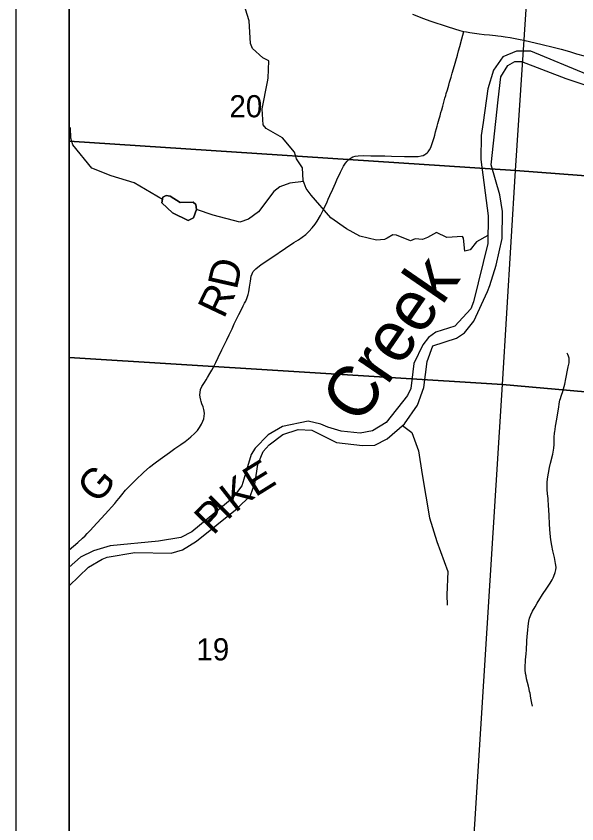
# Model space of a CAD drawing. Extents: x 0 to 34, y 0 to 22.
# Drawn here: x 23.417 to 24.476, y 16.271 to 17.797 of the extents above; entities that cross this region are included whole.
import ezdxf

# ---------------------------------------------------------------- set-up
doc = ezdxf.new("R2010")
doc.units = 0
for name, color, linetype in [('Default', 7, 'Continuous'), ('GM_X_County_Road', 7, 'Continuous'), ('GM_X_County_Road_Text', 7, 'Continuous'), ('GM_X_Major_River', 7, 'Continuous'), ('GM_X_Major_River_Text', 7, 'Continuous'), ('GM_X_Minor_River', 7, 'Continuous'), ('GM_X_Section', 7, 'Continuous'), ('GM_X_Section_Text', 7, 'Continuous'), ('GM_X_Township_Road', 7, 'Continuous'), ('GM_X_Township_Road_Text', 7, 'Continuous'), ('SH_Data', 7, 'Continuous'), ('SH_Text', 7, 'Continuous')]:
    doc.layers.add(name, color=color, linetype=linetype)

msp = doc.modelspace()

# ---------------------------------------------------------------- linework, layer by layer
at = {"layer": 'Default'}
msp.add_lwpolyline([(27.7198, 20.9), (23.5167, 20.9), (23.5167, 16.1239), (23.5888, 16.1195), (25.0535, 16.0331), (25.3458, 16.0191), (26.0811, 15.9921), (26.3691, 15.9829), (26.8773, 15.953), (26.8866, 15.9536), (26.8953, 15.9537)], dxfattribs=at)
for points in [[(23.5167, 17.973), (23.5167, 17.5604), (24.3605, 17.505), (24.3871, 17.9146)], [(23.5167, 17.5604), (23.5167, 17.1515), (24.3357, 17.1007), (24.3605, 17.505)], [(23.5167, 17.1515), (23.5167, 16.1254), (24.2716, 16.0795), (24.3357, 17.1007)]]:
    msp.add_lwpolyline(points, close=True, dxfattribs=at)
at = {"layer": 'GM_X_County_Road'}
for points in [[(24.1653, 17.8003), (24.1861, 17.7921), (24.1983, 17.7879), (24.2332, 17.7767), (24.2551, 17.7699), (24.2629, 17.7678)], [(24.2629, 17.7678), (24.2678, 17.7668), (24.2737, 17.7657), (24.2828, 17.7643), (24.2916, 17.7633), (24.3012, 17.7623), (24.3111, 17.7613), (24.3224, 17.7603), (24.327, 17.7598), (24.3331, 17.7591), (24.3405, 17.7579), (24.3499, 17.7564), (24.3689, 17.7529), (24.3762, 17.7514), (24.4107, 17.7433), (24.4312, 17.738), (24.4466, 17.7343), (24.4621, 17.7298), (24.4755, 17.7258), (24.4898, 17.7216)]]:
    msp.add_lwpolyline(points, dxfattribs=at)
at = {"layer": 'GM_X_Major_River'}
for points in [[(24.4957, 17.6864), (24.3895, 17.7308), (24.3622, 17.7307), (24.3365, 17.7196), (24.3184, 17.6949), (24.3078, 17.6592), (24.2993, 17.5961), (24.2956, 17.5711), (24.295, 17.5259), (24.3089, 17.4194), (24.3079, 17.367), (24.281, 17.2572), (24.2757, 17.2439), (24.2459, 17.2108), (24.2095, 17.1997), (24.1959, 17.1894), (24.1854, 17.1757), (24.168, 17.1407), (24.1625, 17.0929), (24.1561, 17.0799), (24.1157, 17.0289), (24.09, 17.0133), (24.0665, 17.009), (24.0309, 17.0123), (24.0055, 17.0202), (23.9926, 17.0258), (23.9687, 17.0314), (23.9199, 17.0214), (23.893, 17.0057), (23.8681, 16.9806), (23.8605, 16.9684), (23.8467, 16.9217), (23.8429, 16.9091), (23.8248, 16.8852), (23.7484, 16.8223), (23.728, 16.8119), (23.6856, 16.805), (23.5943, 16.7959), (23.5629, 16.7863), (23.5383, 16.7744), (23.5167, 16.7555)], [(24.3328, 17.682), (24.3456, 17.7033), (24.3588, 17.711), (24.3717, 17.711), (24.4552, 17.6791), (24.4665, 17.6753), (24.592, 17.6329)], [(23.5167, 16.7202), (23.5535, 16.7555), (23.5789, 16.7708), (23.5887, 16.7742), (23.641, 16.7835), (23.7095, 16.7823), (23.7311, 16.7884), (23.7576, 16.8049), (23.8343, 16.8666), (23.8596, 16.891), (23.8683, 16.9161), (23.8735, 16.9499), (23.8833, 16.9742), (23.895, 16.9867), (23.9203, 17.0062), (23.9494, 17.0158), (23.9752, 17.0147), (24.0222, 16.9914), (24.0711, 16.9855), (24.0946, 16.986), (24.118, 16.9982), (24.1505, 17.0264), (24.1751, 17.0614), (24.1871, 17.0948), (24.1904, 17.1199), (24.1934, 17.1442), (24.2039, 17.1738), (24.249, 17.1884), (24.2637, 17.1983), (24.2814, 17.2204), (24.3074, 17.2767), (24.3119, 17.2877), (24.3239, 17.3264), (24.3348, 17.3769), (24.3358, 17.4274), (24.3304, 17.4589), (24.3143, 17.5158), (24.3272, 17.6388), (24.3328, 17.682)]]:
    msp.add_lwpolyline(points, dxfattribs=at)
at = {"layer": 'GM_X_Minor_River'}
for points in [[(24.308, 17.3824), (24.2865, 17.3703), (24.2748, 17.3554), (24.2645, 17.3524), (24.2619, 17.3771), (24.26, 17.3805), (24.2304, 17.3786), (24.2111, 17.3881), (24.1937, 17.3785), (24.1846, 17.3747), (24.1705, 17.3759), (24.1618, 17.372), (24.1353, 17.383), (24.1285, 17.3838), (24.1175, 17.3773), (24.1129, 17.375), (24.0978, 17.3735), (24.0659, 17.3811), (24.0409, 17.3947), (24.0113, 17.4156), (23.9742, 17.4585), (23.9644, 17.4714), (23.9591, 17.4859), (23.9576, 17.5102), (23.9466, 17.5269), (23.9424, 17.5398), (23.92, 17.5668), (23.8894, 17.5846), (23.8833, 17.5911), (23.8818, 17.6215), (23.8917, 17.6729), (23.8928, 17.6793), (23.8943, 17.712), (23.883, 17.7181), (23.8633, 17.7356), (23.8598, 17.7451), (23.8568, 17.7876), (23.8436, 17.831)], [(23.6933, 17.45), (23.6399, 17.4817), (23.5963, 17.495), (23.5599, 17.5097), (23.5235, 17.5538), (23.5198, 17.566), (23.5194, 17.5861)], [(23.9597, 17.4842), (23.9337, 17.4809), (23.9147, 17.474), (23.9037, 17.4657), (23.8745, 17.4268), (23.8556, 17.4131), (23.8396, 17.4074), (23.7892, 17.421), (23.7574, 17.4313)], [(23.7574, 17.4313), (23.7521, 17.4157), (23.7415, 17.4107), (23.7123, 17.4251), (23.6922, 17.4441), (23.6941, 17.4544), (23.7002, 17.4578), (23.7074, 17.4567), (23.7263, 17.4449), (23.7513, 17.445), (23.7562, 17.4408), (23.7574, 17.4313)], [(23.6941, 17.4544), (23.6922, 17.4441), (23.7123, 17.4251), (23.7415, 17.4107), (23.7521, 17.4157), (23.7574, 17.4313)], [(23.7574, 17.4313), (23.7562, 17.4408), (23.7513, 17.445), (23.7263, 17.4449), (23.7074, 17.4567), (23.7002, 17.4578), (23.6941, 17.4544)], [(24.147, 17.0235), (24.1643, 17.0101), (24.1768, 16.9755), (24.184, 16.9307), (24.198, 16.8489), (24.2116, 16.8041), (24.2325, 16.7474), (24.2302, 16.7033), (24.2309, 16.6839)]]:
    msp.add_lwpolyline(points, dxfattribs=at)
at = {"layer": 'GM_X_Section'}
for points in [[(25.4267, 17.8394), (25.3999, 17.4262), (24.3605, 17.505), (24.3871, 17.9146)], [(24.3605, 17.505), (25.3999, 17.4262), (25.3722, 17.0086), (24.3357, 17.1007)], [(24.3357, 17.1007), (25.3722, 17.0086), (25.3091, 16.0203), (24.2716, 16.0795)]]:
    msp.add_lwpolyline(points, close=True, dxfattribs=at)
at = {"layer": 'GM_X_Township_Road'}
for points in [[(23.8647, 17.3141), (23.8664, 17.3163), (23.8695, 17.3193), (23.8798, 17.3273), (23.8998, 17.3409), (23.9257, 17.3582), (23.9416, 17.369), (23.95, 17.3743), (23.9573, 17.379), (23.9641, 17.3843), (23.97, 17.3897), (23.9763, 17.3966), (23.982, 17.404), (23.9854, 17.4091), (23.9917, 17.4198), (23.9957, 17.4276), (23.9982, 17.4326), (24.0042, 17.4462), (24.0062, 17.4508), (24.0092, 17.4576), (24.0148, 17.4701), (24.0199, 17.4814), (24.0227, 17.4876), (24.0296, 17.5021), (24.0353, 17.5131), (24.0389, 17.5189), (24.042, 17.5228), (24.0459, 17.5267), (24.0494, 17.5293), (24.0528, 17.5309), (24.0575, 17.5323), (24.0631, 17.533), (24.0724, 17.5333), (24.0867, 17.533), (24.0923, 17.5329), (24.0997, 17.5329), (24.1046, 17.5328), (24.1059, 17.5328), (24.1089, 17.5327), (24.1133, 17.5326), (24.1262, 17.5322), (24.1506, 17.5317), (24.1641, 17.5316), (24.1764, 17.5317), (24.1819, 17.5325), (24.1855, 17.5335), (24.1888, 17.5351), (24.1908, 17.5365), (24.1932, 17.5383), (24.1954, 17.5405), (24.1978, 17.5441), (24.2001, 17.5485), (24.203, 17.556), (24.2064, 17.5674), (24.2076, 17.5721), (24.2093, 17.5781), (24.2111, 17.5847), (24.2123, 17.5889), (24.2136, 17.5937), (24.216, 17.6027), (24.2177, 17.6086), (24.2194, 17.6146), (24.2209, 17.62), (24.2228, 17.6266), (24.2269, 17.6415), (24.2284, 17.6469), (24.2294, 17.6505), (24.2315, 17.6576), (24.2342, 17.6666), (24.2357, 17.6719), (24.2385, 17.6815), (24.2406, 17.689), (24.2429, 17.697), (24.2505, 17.7233), (24.2527, 17.731), (24.2551, 17.7393), (24.259, 17.7536), (24.2629, 17.7678)], [(23.5167, 16.7881), (23.5331, 16.8022), (23.5422, 16.8105), (23.5469, 16.8151), (23.5511, 16.8193), (23.5572, 16.8257), (23.5622, 16.8309), (23.5697, 16.8391), (23.5848, 16.8558), (23.603, 16.8761), (23.6071, 16.8811), (23.6113, 16.8862), (23.6164, 16.8925), (23.6236, 16.901), (23.6292, 16.9068), (23.6365, 16.9145), (23.6458, 16.9236), (23.6539, 16.9313), (23.658, 16.9351), (23.6688, 16.9444), (23.6791, 16.9525), (23.6891, 16.9598), (23.7067, 16.9725), (23.7114, 16.9759), (23.7167, 16.9798), (23.7224, 16.9836), (23.7277, 16.9874), (23.736, 16.9933), (23.7422, 16.9982), (23.7468, 17.0017), (23.7537, 17.008), (23.7591, 17.0139), (23.7633, 17.0194), (23.7671, 17.0258), (23.7697, 17.0314), (23.7712, 17.0361), (23.7722, 17.041), (23.7724, 17.0459), (23.7721, 17.0502), (23.7714, 17.0538), (23.7698, 17.0585), (23.7676, 17.0643), (23.7663, 17.0685), (23.7654, 17.0714), (23.7642, 17.0769), (23.7639, 17.0812), (23.7641, 17.0855), (23.7652, 17.091), (23.7676, 17.0967), (23.7724, 17.1047), (23.7755, 17.1095), (23.7784, 17.1141), (23.7825, 17.1213), (23.7864, 17.1281), (23.7908, 17.1363), (23.7938, 17.1424), (23.7985, 17.1519), (23.8056, 17.1664), (23.8109, 17.1776), (23.8147, 17.1854), (23.819, 17.1943), (23.8247, 17.2062), (23.8289, 17.2151), (23.8346, 17.2268), (23.8376, 17.233), (23.8403, 17.2385), (23.8457, 17.2491), (23.8484, 17.2545), (23.8504, 17.2585), (23.8534, 17.2653), (23.8552, 17.2705), (23.8564, 17.2759), (23.8571, 17.2802), (23.8577, 17.2845), (23.8592, 17.2961), (23.861, 17.3053), (23.8626, 17.31), (23.8642, 17.3133), (23.8647, 17.3141)], [(24.3922, 16.4928), (24.3912, 16.4984), (24.3894, 16.5079), (24.3877, 16.5176), (24.387, 16.5209), (24.386, 16.5252), (24.3846, 16.5308), (24.3813, 16.5446), (24.3802, 16.5504), (24.3794, 16.5544), (24.3786, 16.5618), (24.3786, 16.5659), (24.3786, 16.5699), (24.3789, 16.5759), (24.3792, 16.5804), (24.3798, 16.5859), (24.3803, 16.5916), (24.3809, 16.5996), (24.3811, 16.6043), (24.3815, 16.6102), (24.3819, 16.6164), (24.3824, 16.6243), (24.3828, 16.63), (24.3833, 16.6371), (24.3839, 16.6436), (24.3847, 16.6491), (24.3854, 16.6534), (24.3869, 16.6595), (24.389, 16.6653), (24.3926, 16.6725), (24.3973, 16.6808), (24.4012, 16.6876), (24.4061, 16.6957), (24.4092, 16.701), (24.4111, 16.704), (24.4136, 16.7077), (24.4168, 16.7123), (24.4207, 16.7179), (24.4256, 16.7251), (24.4293, 16.7316), (24.4312, 16.7355), (24.4328, 16.7388), (24.4354, 16.7458), (24.4366, 16.7506), (24.437, 16.7549), (24.4367, 16.7592), (24.4361, 16.7626), (24.4355, 16.7663), (24.4337, 16.7739), (24.4306, 16.7865), (24.4286, 16.7966), (24.4269, 16.8073), (24.426, 16.819), (24.4247, 16.8364), (24.4238, 16.8537), (24.4227, 16.8726), (24.4221, 16.8826), (24.4218, 16.8861), (24.4215, 16.8889), (24.4203, 16.9014), (24.4199, 16.9092), (24.4201, 16.9154), (24.4208, 16.9228), (24.4224, 16.933), (24.4247, 16.9437), (24.4266, 16.9524), (24.4306, 16.9692), (24.4327, 16.9802), (24.4331, 16.9876), (24.4332, 16.9934), (24.4333, 16.9985), (24.4334, 17.0035), (24.4337, 17.0061), (24.434, 17.009), (24.4344, 17.012), (24.435, 17.0157), (24.4359, 17.0219), (24.4383, 17.0354), (24.4419, 17.0587), (24.4427, 17.0633), (24.4436, 17.0679), (24.4443, 17.0709), (24.4452, 17.0745), (24.4465, 17.0785), (24.4479, 17.0827), (24.4488, 17.0857), (24.4511, 17.0926), (24.4536, 17.1014), (24.4542, 17.1048), (24.4547, 17.1081), (24.4599, 17.134), (24.4616, 17.1419), (24.4619, 17.1462), (24.4616, 17.1502), (24.4606, 17.1541), (24.4592, 17.1574), (24.458, 17.1597)]]:
    msp.add_lwpolyline(points, dxfattribs=at)
at = {"layer": 'SH_Data'}
for points in [[(23.4167, 21), (30.4167, 21), (30.4167, 14), (23.4167, 14)], [(23.5167, 20.9), (30.3167, 20.9), (30.3167, 14.1), (23.5167, 14.1)]]:
    msp.add_lwpolyline(points, close=True, dxfattribs=at)
at = {"layer": 'SH_Text'}
msp.add_lwpolyline([(30.3167, 20.9), (23.5167, 20.9), (23.5167, 14.1), (29.5051, 14.1)], dxfattribs=at)

# ---------------------------------------------------------------- texts
at = {"layer": 'GM_X_County_Road_Text'}
for s, rotation, p in [('E', 31.8623, (23.8684, 16.8871)), ('K', 37.9256, (23.8303, 16.8572)), ('P', 46.0248, (23.7889, 16.8144)), ('I', 45.5547, (23.8154, 16.8419))]:
    msp.add_text(s, height=0.0568, rotation=rotation, dxfattribs=at).set_placement(p)
at = {"layer": 'GM_X_Major_River_Text'}
msp.add_text('Creek', height=0.0947, rotation=55.5148, dxfattribs=at).set_placement((24.0659, 17.0221))
at = {"layer": 'GM_X_Section_Text'}
for s, p in [('20', (23.8196, 17.6056)), ('19', (23.7571, 16.5794))]:
    msp.add_text(s, height=0.04186, rotation=0, dxfattribs=at).set_placement(p)
at = {"layer": 'GM_X_Township_Road_Text'}
for s, rotation, p in [('D', 77.2345, (23.8334, 17.2784)), ('R', 64.56, (23.809, 17.2235)), ('G', 49.4537, (23.5705, 16.8734))]:
    msp.add_text(s, height=0.0568, rotation=rotation, dxfattribs=at).set_placement(p)

doc.saveas('drawing.dxf')
